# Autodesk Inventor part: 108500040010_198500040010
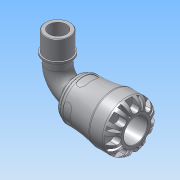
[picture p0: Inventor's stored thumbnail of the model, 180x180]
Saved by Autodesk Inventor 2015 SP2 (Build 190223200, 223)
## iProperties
Created: 2016-12
Part Number: 108500040010_198500040010
Material: PVC-Piping
Description: PLASSON 90° ELBOW WITH THREADED MALE OFFTAKE 40X1" SERIES 1
Document SubType Name: Modeling
Designer: KIM
Mass: 664.223 g
Surface Area: 733.008 cm^2
Volume: 474.445 cm^3
Density: 1.4 g/cm^3
Appearance: Smooth - White
Author: KIM
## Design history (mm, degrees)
derived "1085.ipt"
feature "Solid1::1085.ipt"
tag "TaggingFeature1"
body "Solid1"
other parameters: "d1" = 29.82, "d8" = 59.5, "d13" = 8, "d14" = 8, "d15" = 0, "d17" = 360 deg, "d19" = 8 deg, "d20" = 0.8, "d21" = 0.8, "d22" = 8 deg, "d24" = 0, "d26" = 360 deg, "d33" = 7, "d43" = 54.6, "d51" = 0.7, "d54" = 14, "d55" = 8.8, "d57" = 15.68, "d58" = 0, "d74" = 0, "d78" = 71, "d82" = 0.8, "d115" = 360 deg, "d207" = 90 deg, "d228" = 11.9, "d247" = 1.4, "d248" = 4.26, "d268" = 32.725, "d269" = 4.26, "d270" = 107, "d276" = 33.249, "d277" = 19, "d278" = 36.5739, "d279" = 57, "d280" = 20.9, "d281" = 4.98735, "d283" = 29.9241, "d286" = 0, "d287" = 0, "d288" = 23.2743, "d290" = 12.33795, "d292" = 30 deg, "l_" = 71, "A_" = 107, "A_1" = 57, "l_2" = 19, "R_" = 33.249, "d9" = 10, "d289" = 23.2743
